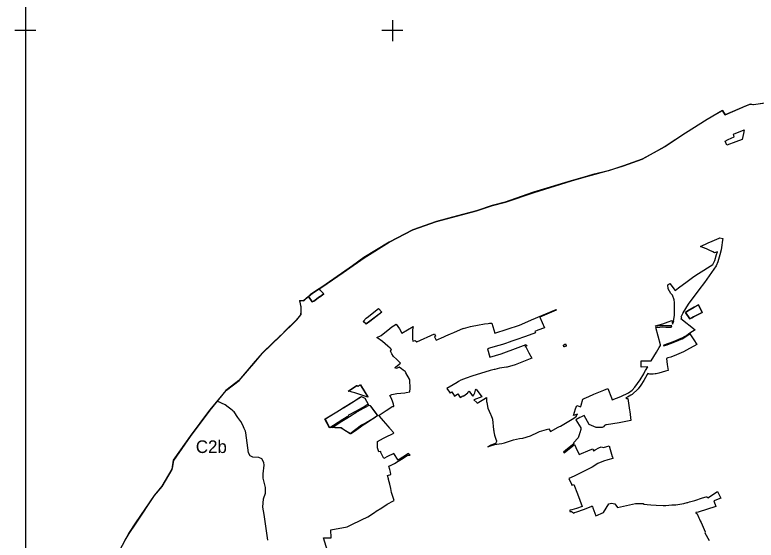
# Model space of a CAD drawing. Extents: x -478490 to -472450, y -1118050 to -1109550.
# Drawn here: x -478490 to -474975, y -1116218 to -1113725 of the extents above; entities that cross this region are included whole.
import ezdxf

# ---------------------------------------------------------------- set-up
doc = ezdxf.new("R2010")
doc.units = 0
for name, color, linetype in [('hranice kú', 7, 'Continuous'), ('Implicitní', 7, 'Continuous'), ('ObPÚ', 7, 'Continuous')]:
    doc.layers.add(name, color=color, linetype=linetype)

msp = doc.modelspace()

# ---------------------------------------------------------------- linework, layer by layer
at = {"layer": 'hranice kú'}
for p, q in [((-475022.9, -1114156.5), (-475122.4, -1114199.6)), ((-475002.4, -1114148.5), (-475022.9, -1114156.5)), ((-474987.2, -1114152.5), (-475002.4, -1114148.5)), ((-474886, -1114137.7), (-474987.2, -1114152.5)), ((-475134, -1114179), (-475207.8, -1114221.5)), ((-475122.4, -1114199.6), (-475134, -1114179)), ((-475207.8, -1114221.5), (-475309.6, -1114286.2)), ((-475309.6, -1114286.2), (-475401.1, -1114346.7)), ((-475401.1, -1114346.7), (-475408.2, -1114351.3)), ((-475408.2, -1114351.3), (-475516.2, -1114410.6)), ((-475516.2, -1114410.6), (-475603.8, -1114442.4)), ((-475603.8, -1114442.4), (-475675.9, -1114464.8)), ((-475748.8, -1114483.6), (-475774.2, -1114490.1)), ((-475675.9, -1114464.8), (-475748.8, -1114483.6)), ((-475851.9, -1114513.6), (-476030.1, -1114567.2)), ((-475774.2, -1114490.1), (-475851.9, -1114513.6)), ((-476089.1, -1114587.7), (-476165.8, -1114614.4)), ((-476030.1, -1114567.2), (-476089.1, -1114587.7)), ((-476165.8, -1114614.4), (-476226.9, -1114630.6)), ((-476300.5, -1114656.1), (-476390.6, -1114678.9)), ((-476226.9, -1114630.6), (-476300.5, -1114656.1)), ((-476390.6, -1114678.9), (-476491.3, -1114705.4)), ((-476491.3, -1114705.4), (-476602.9, -1114745.8)), ((-476602.9, -1114745.8), (-476714.7, -1114803.6)), ((-476714.7, -1114803.6), (-476835.3, -1114877.2)), ((-476835.3, -1114877.2), (-476889.8, -1114915.9)), ((-476889.8, -1114915.9), (-477034.1, -1115017.7)), ((-477079.5, -1115046.1), (-477089.2, -1115054.5)), ((-477047.8, -1115026.2), (-477079.5, -1115046.1)), ((-477034.1, -1115017.7), (-477047.8, -1115026.2)), ((-477121, -1115082.3), (-477141, -1115082)), ((-477141, -1115082), (-477133.6, -1115111.5)), ((-477098.4, -1115062.6), (-477121, -1115082.3)), ((-477089.2, -1115054.5), (-477098.4, -1115062.6)), ((-477133.6, -1115111.5), (-477134.2, -1115129.3)), ((-477134.7, -1115147.1), (-477142.3, -1115156.6)), ((-477134.2, -1115129.3), (-477134.7, -1115147.1)), ((-477155, -1115172.4), (-477210.7, -1115227.9)), ((-477142.3, -1115156.6), (-477155, -1115172.4)), ((-477233.1, -1115250.4), (-477267, -1115282.3)), ((-477229.4, -1115246.9), (-477233.1, -1115250.4)), ((-477216.6, -1115233.9), (-477229.4, -1115246.9)), ((-477214.6, -1115231.9), (-477216.6, -1115233.9)), ((-477210.7, -1115227.9), (-477214.6, -1115231.9)), ((-477267, -1115282.3), (-477317.9, -1115330.4)), ((-477317.9, -1115330.4), (-477350, -1115369.3)), ((-477350, -1115369.3), (-477428.5, -1115460.9)), ((-477428.5, -1115460.9), (-477490.1, -1115508.2)), ((-477490.1, -1115508.2), (-477566.2, -1115601.8)), ((-477566.2, -1115601.8), (-477658.2, -1115726.7)), ((-477658.2, -1115726.7), (-477738.5, -1115840.6)), ((-477738.5, -1115840.6), (-477743.9, -1115876.8)), ((-477745.7, -1115882.6), (-477792.7, -1115963.5)), ((-477743.9, -1115876.8), (-477745.7, -1115882.6)), ((-477792.7, -1115963.5), (-477829.2, -1116007.1)), ((-477829.2, -1116007.1), (-477917, -1116137.1)), ((-477917, -1116137.1), (-477949.4, -1116186.8)), ((-477949.4, -1116186.8), (-477967.8, -1116218.8))]:
    msp.add_line(p, q, dxfattribs=at)
at = {"layer": 'Implicitní'}
for p, q in [((-478440.1, -1113750.1), (-478440.1, -1113850.1)), ((-478440.1, -1113750.1), (-478440.1, -1113850.1)), ((-478440.1, -1113750.1), (-478440.1, -1113850.1)), ((-478440.1, -1113750.1), (-478440.1, -1113850.1)), ((-478440.1, -1113750.1), (-478440.1, -1113850.1)), ((-478440.1, -1113750.1), (-478440.1, -1113850.1)), ((-478440.1, -1113750.1), (-478440.1, -1113850.1)), ((-478440.1, -1113750.1), (-478440.1, -1113850.1)), ((-476700.1, -1113750.1), (-476700.1, -1113850.1)), ((-476700.1, -1113750.1), (-476700.1, -1113850.1)), ((-476700.1, -1113750.1), (-476700.1, -1113850.1)), ((-476700.1, -1113750.1), (-476700.1, -1113850.1)), ((-476700.1, -1113750.1), (-476700.1, -1113850.1)), ((-476700.1, -1113750.1), (-476700.1, -1113850.1)), ((-476700.1, -1113750.1), (-476700.1, -1113850.1)), ((-476700.1, -1113750.1), (-476700.1, -1113850.1)), ((-478390.1, -1113800.1), (-478490.1, -1113800.1)), ((-478390.1, -1113800.1), (-478490.1, -1113800.1)), ((-478390.1, -1113800.1), (-478490.1, -1113800.1)), ((-478390.1, -1113800.1), (-478490.1, -1113800.1)), ((-478390.1, -1113800.1), (-478490.1, -1113800.1)), ((-478390.1, -1113800.1), (-478490.1, -1113800.1)), ((-478390.1, -1113800.1), (-478490.1, -1113800.1)), ((-476650.1, -1113800.1), (-476750.1, -1113800.1)), ((-476650.1, -1113800.1), (-476750.1, -1113800.1)), ((-476650.1, -1113800.1), (-476750.1, -1113800.1)), ((-476650.1, -1113800.1), (-476750.1, -1113800.1)), ((-476650.1, -1113800.1), (-476750.1, -1113800.1)), ((-476650.1, -1113800.1), (-476750.1, -1113800.1)), ((-476650.1, -1113800.1), (-476750.1, -1113800.1))]:
    msp.add_line(p, q, dxfattribs=at)
msp.add_lwpolyline([(-478440.1, -1118000.1), (-472500.1, -1118000.1), (-472500.1, -1109600.1), (-478440.1, -1109600.1)], close=True, dxfattribs=at)
msp.add_lwpolyline([(-477290.1, -1116218.2), (-477307.4, -1116096.5), (-477314.6, -1116061), (-477310.7, -1116023), (-477302.3, -1115994.9), (-477301.2, -1115968), (-477312.4, -1115923.9), (-477312, -1115903.3), (-477307.7, -1115862), (-477309.2, -1115849), (-477319.7, -1115832.3), (-477333.1, -1115826.6), (-477361.3, -1115824.1), (-477373.9, -1115818.6), (-477382.1, -1115804.4), (-477394.5, -1115708.3), (-477396.9, -1115701.8), (-477398.4, -1115697.9), (-477402.6, -1115688.6), (-477408.8, -1115672.3), (-477418.7, -1115655), (-477432.4, -1115635.9), (-477450.9, -1115610.1), (-477455.1, -1115605.5), (-477460.2, -1115601.4), (-477465.7, -1115597.1), (-477478.8, -1115587.9), (-477493.1, -1115576.5), (-477530.1, -1115558.5)], dxfattribs=at)
at = {"layer": 'ObPÚ'}
for p, q in [((-476795.8, -1115142.9), (-476765.1, -1115119.2)), ((-476765.1, -1115119.2), (-476749.5, -1115136)), ((-476823.6, -1115164), (-476813.4, -1115156.5)), ((-476813.4, -1115156.5), (-476795.8, -1115142.9)), ((-476749.5, -1115136), (-476807.4, -1115179.7)), ((-476838.6, -1115180.4), (-476823.6, -1115164)), ((-476823.5, -1115192.3), (-476838.6, -1115180.4)), ((-476807.4, -1115179.7), (-476823.5, -1115192.3)), ((-476909, -1115510.7), (-476870.1, -1115484.8)), ((-476870.1, -1115484.8), (-476863.3, -1115487.6)), ((-476863.3, -1115487.6), (-476852.1, -1115480.5)), ((-476852.1, -1115480.5), (-476817.4, -1115537.3)), ((-476900.7, -1115512.2), (-476909, -1115510.7)), ((-476891.2, -1115515.2), (-476900.7, -1115512.2)), ((-476878.5, -1115519.2), (-476891.2, -1115515.2)), ((-476816.7, -1115540.2), (-476878.5, -1115519.2)), ((-476817.4, -1115537.3), (-476816.7, -1115540.2))]:
    msp.add_line(p, q, dxfattribs=at)
for points in [[(-477992.6, -1116266.4), (-477967.7, -1116217.9), (-477949, -1116186), (-477916, -1116136), (-477827.8, -1116006.6), (-477791.1, -1115962.3), (-477744.4, -1115881.6), (-477737.4, -1115839.5), (-477657.3, -1115725.4), (-477565.5, -1115600.8), (-477486.9, -1115507), (-477426, -1115461.1), (-477348, -1115368.5), (-477315.2, -1115330.2), (-477231.4, -1115250.6), (-477154.2, -1115173.6), (-477134.2, -1115148.8), (-477133.2, -1115130.3), (-477132.1, -1115111.9), (-477138.9, -1115081.3), (-477119.7, -1115082.7), (-477097.2, -1115062.7), (-477080.6, -1115086.8), (-477072.5, -1115083.8), (-477045.9, -1115063.6), (-477043.9, -1115064.1), (-477025.3, -1115049.6), (-477043.5, -1115030.7), (-477047.5, -1115026.1), (-477033.7, -1115018.2), (-476934, -1114947.9), (-476834.4, -1114877.8), (-476714.6, -1114803.8), (-476602.9, -1114745.9), (-476491.3, -1114705.5), (-476390.2, -1114678.8), (-476300.7, -1114655.7), (-476225.2, -1114630.7), (-476164.4, -1114614.7), (-476028.4, -1114567.7), (-475850.6, -1114513.7), (-475773.2, -1114490.1), (-475675.4, -1114464.4), (-475603.9, -1114441.6), (-475515.6, -1114410.1), (-475407.7, -1114350.6), (-475310.4, -1114285.4), (-475208.2, -1114220.8), (-475134, -1114178.4), (-475121.9, -1114199.1), (-475023.6, -1114156.4), (-475002.8, -1114148.9), (-474998, -1114149.5), (-474990.2, -1114150.6), (-474989.1, -1114150.8), (-474987.5, -1114151), (-474886.4, -1114137.2)], [(-475031.6, -1114270.7), (-475035.2, -1114288.3), (-475041.6, -1114317.3), (-475071, -1114328.2), (-475113.6, -1114343.8), (-475122.4, -1114325.3), (-475107.2, -1114316.9), (-475078.7, -1114304.2), (-475082.7, -1114291.8), (-475031.6, -1114270.7)], [(-475148.1, -1114784.1), (-475132.8, -1114786.1), (-475134.1, -1114794.3), (-475139.6, -1114829.2), (-475141.4, -1114840.6), (-475147, -1114864.5), (-475156.6, -1114896.8), (-475164.7, -1114915.7), (-475219.8, -1114995.7), (-475246.4, -1115030.8), (-475297.9, -1115099.1), (-475322.5, -1115139.2), (-475323.4, -1115141.1), (-475326.2, -1115147.8), (-475332.4, -1115160.1), (-475329.7, -1115162.2), (-475332.8, -1115166.5), (-475264.7, -1115220.3), (-475289.6, -1115235.6), (-475304.6, -1115246.6), (-475313.5, -1115251.8), (-475327.3, -1115259.4), (-475332.9, -1115262), (-475368.8, -1115277.8), (-475390.2, -1115285.2), (-475413.5, -1115293), (-475413.9, -1115295.5), (-475414.6, -1115296.5), (-475396.8, -1115290.7), (-475381.9, -1115285.4), (-475368.1, -1115280.4), (-475352.2, -1115273.9), (-475342, -1115269.3), (-475326, -1115262.1), (-475313, -1115254.8), (-475303.1, -1115249.2), (-475289.4, -1115239.2), (-475271.1, -1115267.1), (-475256.4, -1115289.3), (-475305.6, -1115316.7), (-475319, -1115324.5), (-475352.1, -1115339), (-475379.3, -1115349.1), (-475393.3, -1115353.4), (-475400.3, -1115356), (-475396.5, -1115385.4), (-475392.7, -1115413), (-475404.3, -1115416.8), (-475436.9, -1115425.3), (-475448.5, -1115428.4), (-475454.5, -1115429.6), (-475463.7, -1115430.8), (-475472.8, -1115431.1), (-475479.9, -1115430.5), (-475488.1, -1115428), (-475488.8, -1115427.8), (-475491.2, -1115432.3), (-475508.3, -1115461.2), (-475522.4, -1115482.1), (-475534.8, -1115500.6), (-475562.6, -1115526.6), (-475569.6, -1115530.7), (-475585.2, -1115539.6), (-475592.6, -1115543.6), (-475588.6, -1115546.6), (-475584.2, -1115546.5), (-475575.5, -1115600.7), (-475574.6, -1115607), (-475568.6, -1115650.4), (-475601.1, -1115656.6), (-475624.5, -1115661.2), (-475654.2, -1115666.4), (-475684.3, -1115671.3), (-475687.2, -1115670.6), (-475693.7, -1115674.8), (-475699, -1115680.1), (-475705.7, -1115683.9), (-475709.8, -1115683.9), (-475733.4, -1115683.1), (-475767, -1115669.8), (-475790, -1115626.6), (-475799.8, -1115631.5), (-475804, -1115633.4), (-475810.7, -1115636.7), (-475829.7, -1115648), (-475814.9, -1115672), (-475806.3, -1115684.8), (-475806.3, -1115693.2), (-475811.6, -1115709.7), (-475812.7, -1115712.9), (-475812.9, -1115713.5), (-475819.1, -1115732.4), (-475841.2, -1115755.7), (-475838.5, -1115760.3), (-475845.9, -1115766.1), (-475877.4, -1115790.5)], [(-475218.2, -1114832.5), (-475219.5, -1114831.9), (-475238.7, -1114824.8), (-475202.4, -1114807.1), (-475184, -1114798.8), (-475149.9, -1114784.6), (-475148.1, -1114784.1)], [(-476080.7, -1115733.9), (-476044.6, -1115722.8), (-476009.2, -1115705.3), (-476006, -1115704.3), (-476001.7, -1115702.9), (-475992.1, -1115700.1), (-475958.5, -1115689.8), (-475951, -1115702.6), (-475913.8, -1115682.5), (-475907.2, -1115679.6), (-475903.4, -1115677.7), (-475840.3, -1115639.7), (-475827.1, -1115629.9), (-475826.5, -1115627.2), (-475822.6, -1115620.1), (-475841.5, -1115626.4), (-475831.2, -1115595.6), (-475825.9, -1115579.1), (-475807.2, -1115585.2), (-475804.9, -1115577.5), (-475797.7, -1115549), (-475791.1, -1115546.2), (-475768.3, -1115535.9), (-475744.5, -1115525.5), (-475728.4, -1115519.2), (-475712.4, -1115512.7), (-475696.6, -1115506.6), (-475678, -1115499.1), (-475661.4, -1115542.5), (-475657.5, -1115552.7), (-475617.2, -1115536.5), (-475580, -1115519.1), (-475562.6, -1115505.8), (-475549.8, -1115492.6), (-475525.8, -1115458.2), (-475508.2, -1115428.6), (-475505.8, -1115425), (-475499.2, -1115413), (-475489.2, -1115395.3), (-475521.1, -1115396.7), (-475521.1, -1115367.4), (-475509.5, -1115367.4), (-475488.5, -1115367.2), (-475472.4, -1115366.6), (-475447.9, -1115326.5), (-475434.6, -1115304.4), (-475428.9, -1115294.7), (-475429.3, -1115291.8), (-475450.3, -1115208.5), (-475431.9, -1115206.9), (-475417.8, -1115206.3), (-475403.1, -1115207.2), (-475398.3, -1115207.7), (-475379.8, -1115208.2), (-475378.3, -1115208.3), (-475374.8, -1115201.4), (-475389.4, -1115201.4), (-475396.2, -1115201.5), (-475432.4, -1115201.7), (-475451.6, -1115203.6), (-475452.3, -1115200.8), (-475417.3, -1115191.5), (-475392.6, -1115182.3), (-475375.7, -1115175.9), (-475373.5, -1115183.9), (-475371.1, -1115193.9), (-475364.9, -1115179.2), (-475366.7, -1115178.5), (-475362.9, -1115152.1), (-475362.8, -1115131.7), (-475362.6, -1115116.2), (-475362.9, -1115105.9), (-475363, -1115101.2), (-475363, -1115098.2), (-475361.8, -1115090.2), (-475364.3, -1115077.5), (-475372.3, -1115055.4), (-475379.1, -1115047.3), (-475391.9, -1115024.9), (-475393.8, -1115006.5), (-475383.9, -1114999.9), (-475359.1, -1115032.8), (-475343.3, -1115021.2), (-475301.6, -1114990.1), (-475295.5, -1114985.5), (-475271.4, -1114967.5), (-475248.6, -1114952.7), (-475181.1, -1114910.8), (-475171.1, -1114890.7), (-475163.2, -1114863.4), (-475159.1, -1114849.7), (-475173.1, -1114854.9), (-475181, -1114850.7), (-475198.3, -1114841.7), (-475207.7, -1114837.2), (-475218.2, -1114832.5)], [(-477047.5, -1115026.1), (-477043.5, -1115030.7), (-477025.3, -1115049.6), (-477043.9, -1115064.1), (-477045.9, -1115063.6), (-477072.5, -1115083.8), (-477080.6, -1115086.8), (-477097.2, -1115062.7), (-477088.2, -1115054.8), (-477078.9, -1115046), (-477062.1, -1115035), (-477047.5, -1115026.1)], [(-476765.5, -1115119.5), (-476749.7, -1115136.3), (-476807.4, -1115180.3), (-476823.5, -1115192.5), (-476838.5, -1115180.6), (-476823.2, -1115163.8), (-476813.4, -1115156.1), (-476796, -1115142.8), (-476765.5, -1115119.5)], [(-476755.5, -1115799), (-476755.8, -1115798), (-476764.4, -1115799.6), (-476770.5, -1115780.2), (-476771, -1115765.2), (-476770.2, -1115749.7), (-476741.8, -1115734.8), (-476732, -1115729.7), (-476696.8, -1115711.7), (-476692.5, -1115709.2), (-476710.4, -1115689.4), (-476712.4, -1115687.1), (-476720, -1115678.1), (-476742.3, -1115651.6), (-476761.2, -1115630.1), (-476764.4, -1115626.4), (-476763, -1115625.6), (-476729.7, -1115602.9), (-476697.2, -1115582.4), (-476694.7, -1115586.2), (-476693.6, -1115580.2), (-476694.2, -1115572.8), (-476699.2, -1115558.8), (-476706, -1115542.3), (-476712.2, -1115531.2), (-476708.5, -1115529.6), (-476702.9, -1115527.4), (-476678.2, -1115523.1), (-476641.2, -1115518.6), (-476634.7, -1115517.8), (-476617.1, -1115514.8), (-476616.1, -1115497.4), (-476616.8, -1115459.6), (-476619.4, -1115454.6), (-476636.7, -1115424.2), (-476638.2, -1115419.2), (-476639.6, -1115417.9), (-476648.1, -1115411.8), (-476657.2, -1115405.2), (-476667.7, -1115397.8), (-476668.1, -1115397.6), (-476680.6, -1115404.3), (-476688.9, -1115400.3), (-476683.5, -1115395.6), (-476662.2, -1115377.8), (-476669.9, -1115369.8), (-476680.8, -1115358.9), (-476694.9, -1115346.1), (-476702.3, -1115334.6), (-476708.2, -1115320.9), (-476704.6, -1115313.1), (-476707.2, -1115310.4), (-476710.6, -1115306.8), (-476721, -1115296.9), (-476747.1, -1115275.5), (-476773.1, -1115256.3), (-476753.8, -1115247.8), (-476712.6, -1115214.6), (-476702.4, -1115206.3), (-476694.3, -1115201.1), (-476681.6, -1115192.9), (-476666.8, -1115216), (-476654.4, -1115235.6), (-476600.8, -1115204.3), (-476604, -1115219.8), (-476604.3, -1115242.1), (-476604.4, -1115257.8), (-476603.8, -1115263.8), (-476602.2, -1115273.2), (-476591.8, -1115271.3), (-476584.8, -1115277.5), (-476501, -1115239.4), (-476495.6, -1115250.2), (-476500.4, -1115252.6), (-476492.4, -1115268.6), (-476455.9, -1115252.7), (-476446, -1115248.3), (-476423.8, -1115238.9), (-476408.7, -1115232.4), (-476362.8, -1115211.5), (-476363.1, -1115214.2), (-476329.8, -1115204.9), (-476321.4, -1115203.2), (-476295.6, -1115198.1), (-476262.7, -1115192.2), (-476245.3, -1115189.6), (-476239, -1115188.4), (-476229.4, -1115189.3), (-476228.4, -1115189.3), (-476213.9, -1115236.2), (-476097.8, -1115198.2), (-476044, -1115174.6), (-476040.4, -1115173.1), (-475923.9, -1115123.8), (-475922.9, -1115126.6), (-476001.2, -1115160.1)], [(-476001.2, -1115160.1), (-475978.5, -1115210.4), (-476010.9, -1115222.5), (-476024.9, -1115227.8), (-476022.1, -1115234.1), (-476068.7, -1115252.3), (-476114.9, -1115267.7), (-476138.6, -1115276), (-476141.9, -1115277.2), (-476168.5, -1115286.4), (-476178.6, -1115289.9), (-476195.4, -1115294.7), (-476223, -1115302.6), (-476238.7, -1115307), (-476249.6, -1115310.1), (-476237.8, -1115350.3), (-476184.5, -1115334.3), (-476103.8, -1115304.7), (-476065.3, -1115290.1), (-476062.5, -1115296.4), (-476072.5, -1115299), (-476067.4, -1115300.8), (-476057.5, -1115319.9), (-476052.6, -1115329.4), (-476039.5, -1115354.8), (-476078.4, -1115369.8), (-476117, -1115385.5), (-476155.8, -1115397), (-476158.1, -1115397.3), (-476191.7, -1115401.9), (-476214.9, -1115407.7), (-476217.9, -1115408.5), (-476236.6, -1115413.2), (-476323, -1115439.7), (-476350.1, -1115449), (-476375, -1115459), (-476385.9, -1115464.8), (-476392.2, -1115469.7), (-476411, -1115480.8), (-476441.4, -1115498.3), (-476428.9, -1115516.6), (-476426.7, -1115520.2), (-476425.5, -1115519.4), (-476418.1, -1115514.4), (-476406.1, -1115534.8), (-476390, -1115524.6), (-476377.8, -1115542), (-476366.1, -1115533.4), (-476364.4, -1115535.6), (-476361.5, -1115533.8), (-476342.9, -1115519.2), (-476343.8, -1115517.9), (-476335.7, -1115511.8), (-476321.2, -1115532.1), (-476318.9, -1115534.9), (-476313, -1115528.6), (-476309.8, -1115518.6), (-476305.3, -1115506.9), (-476302.5, -1115502), (-476275.6, -1115537.5), (-476313.2, -1115552.2), (-476300.2, -1115565.6), (-476297.2, -1115568.2), (-476265.8, -1115548.7), (-476253.2, -1115541.5), (-476254.2, -1115545.1), (-476254.1, -1115560.3), (-476252.9, -1115565.5), (-476247.1, -1115591.9), (-476235, -1115620.9), (-476233.9, -1115623.6), (-476227.1, -1115639.9), (-476225.4, -1115644.4), (-476220, -1115694.3), (-476219.8, -1115696.3), (-476219.6, -1115698.6), (-476218.9, -1115704.2), (-476216.5, -1115719.8), (-476214.9, -1115724.1), (-476208.9, -1115738.8), (-476206.5, -1115747), (-476206.4, -1115750.3), (-476211.4, -1115759.3), (-476232.4, -1115767.1), (-476247.2, -1115775.1), (-476229.9, -1115769.6), (-476218.5, -1115766.3), (-476210.1, -1115762.7), (-476205.2, -1115762.3), (-476193.3, -1115761.9), (-476181.7, -1115759.9), (-476167.6, -1115755.9), (-476126.1, -1115741.6), (-476097.4, -1115735.9), (-476082.4, -1115734.1), (-476080.7, -1115733.9)], [(-475878.6, -1115287.3), (-475875.6, -1115294.7), (-475876.6, -1115295.2), (-475876.2, -1115296.1), (-475875.8, -1115297), (-475885.9, -1115301.2), (-475886.3, -1115300.2), (-475888.6, -1115293.7), (-475887, -1115293.1), (-475887.8, -1115291.1), (-475878.6, -1115287.3)], [(-476851.2, -1115480.9), (-476816.7, -1115537.6), (-476815.9, -1115540.5), (-476877.8, -1115519.3), (-476890.3, -1115515.3), (-476899.7, -1115512.3), (-476908, -1115510.6), (-476869, -1115484.9), (-476862.3, -1115487.4), (-476851.2, -1115480.9)], [(-476845.8, -1115536.8), (-476833.2, -1115543.1), (-476830.3, -1115545.2), (-476814.1, -1115573.4), (-476829.7, -1115582.6), (-476871.8, -1115606), (-476907.9, -1115625.4), (-476911.4, -1115631), (-476914.7, -1115633.2), (-476935, -1115646.2), (-476979.5, -1115674.5), (-476996.8, -1115685.2), (-477019.2, -1115643.1), (-476956.1, -1115604.4), (-476941.7, -1115595.5), (-476928.8, -1115587.7), (-476892.8, -1115565.7), (-476851.6, -1115540.4), (-476845.8, -1115536.8)], [(-476810.1, -1115578.3), (-476805.9, -1115579.4), (-476804.7, -1115580.3), (-476803.4, -1115582.1), (-476792.3, -1115597.6), (-476773.7, -1115623.2), (-476770.2, -1115628.1), (-476787.4, -1115639.3), (-476804.2, -1115650.6), (-476823.1, -1115663.3), (-476837.9, -1115672.8), (-476847.1, -1115679.5), (-476850.6, -1115681.9), (-476879.3, -1115702.4), (-476896.2, -1115714.4), (-476899, -1115714.2), (-476930.7, -1115694), (-476942.5, -1115685.1), (-476965.9, -1115685.2), (-476984.4, -1115683.5), (-476947.9, -1115658.3), (-476916.7, -1115638.9), (-476890.7, -1115623.1), (-476880.5, -1115616.9), (-476873.4, -1115612.5), (-476851.1, -1115600.2), (-476833, -1115590.3), (-476824.8, -1115585.7), (-476813, -1115578.7), (-476810.1, -1115578.3)], [(-475877.4, -1115790.5), (-475888.6, -1115801.4), (-475886, -1115804.2), (-475836, -1115764.4), (-475833.6, -1115770.2), (-475830.2, -1115777.9), (-475814.8, -1115812), (-475761.7, -1115789.4), (-475749.3, -1115784.9), (-475746.8, -1115794.7), (-475738, -1115789.5), (-475721.7, -1115779.9), (-475710.7, -1115775.7), (-475699.7, -1115779.1), (-475672.1, -1115771.2), (-475667.3, -1115787.5), (-475657.2, -1115821.4), (-475656.6, -1115823.4), (-475654.6, -1115830.4), (-475677.9, -1115836.7), (-475698.4, -1115843.4), (-475726.3, -1115854.9), (-475753.2, -1115871.8), (-475796.4, -1115894.5), (-475838.6, -1115914.6), (-475863.6, -1115925.3), (-475850.8, -1115952.1), (-475848.8, -1115957.6), (-475839.8, -1115954), (-475822.7, -1115998.9), (-475799.8, -1116058.4), (-475826.7, -1116067.4), (-475849.1, -1116073.9), (-475859, -1116076.8), (-475858.5, -1116081.8), (-475850.5, -1116082.4), (-475846, -1116085.5), (-475841.5, -1116090.5), (-475835.8, -1116087.6), (-475824.7, -1116084.4), (-475793.6, -1116073.2), (-475757.8, -1116058.6), (-475752.6, -1116055.2), (-475751.9, -1116056.2), (-475751.3, -1116058.9), (-475749.1, -1116064.3), (-475735.2, -1116103), (-475699, -1116087), (-475673.7, -1116045.3), (-475661.5, -1116042.2), (-475645.4, -1116045.7), (-475632.5, -1116062.8), (-475547.6, -1116045), (-475509.3, -1116044.8), (-475509.4, -1116046.9), (-475475.1, -1116050.7), (-475449.8, -1116052.2), (-475416.4, -1116053.9), (-475403.4, -1116053.3), (-475374.7, -1116051.3), (-475356.5, -1116050.4), (-475317.7, -1116043.9), (-475302.2, -1116039.9), (-475298.9, -1116039.2), (-475291.5, -1116036.7), (-475266.1, -1116030), (-475230.2, -1116017.8), (-475212.6, -1116013.1), (-475209, -1116012.4), (-475205, -1116017.9), (-475157.9, -1115986.7), (-475143.1, -1116018.7), (-475171.7, -1116030.3), (-475175.1, -1116031.6), (-475166.6, -1116058.8), (-475250, -1116085.1), (-475260.4, -1116087.5), (-475261.4, -1116089.2), (-475254.8, -1116092.9), (-475246.3, -1116113), (-475243.5, -1116119.3), (-475240.6, -1116126), (-475236.6, -1116135), (-475217.4, -1116178.1), (-475216.4, -1116180.6), (-475219.2, -1116183.5), (-475197.7, -1116219.3)], [(-477007.9, -1116269), (-477025.9, -1116207.4), (-476990.5, -1116207), (-476992.4, -1116169.7), (-476913.9, -1116154.4), (-476895, -1116145), (-476846.1, -1116121.6), (-476816.5, -1116106.9), (-476785, -1116086.7), (-476776.6, -1116081.3), (-476750.7, -1116064.8), (-476724.3, -1116048.2), (-476695, -1116031.9), (-476691.4, -1116029.9), (-476697.9, -1116011.9), (-476703.4, -1115992.7), (-476707.7, -1115973.2), (-476712.7, -1115953.4), (-476717.9, -1115931.2), (-476718.9, -1115926.7), (-476722.5, -1115911.7), (-476708, -1115906.3), (-476706.6, -1115905.8), (-476709.3, -1115896.3), (-476712.4, -1115883.4), (-476716.3, -1115867), (-476706.5, -1115862.8), (-476689.2, -1115855), (-476672.4, -1115844.1), (-476656.2, -1115833.3), (-476639.8, -1115822.5), (-476624.6, -1115814.3), (-476615.7, -1115814.8), (-476624, -1115806.8), (-476672.6, -1115838.9), (-476693.6, -1115807.2), (-476722.7, -1115821.8), (-476740.9, -1115830.8), (-476754.6, -1115802.9), (-476755.5, -1115799)]]:
    msp.add_lwpolyline(points, dxfattribs=at)
for points in [[(-475309.6, -1115137.3), (-475298.3, -1115130.6), (-475298.9, -1115129.2), (-475268.3, -1115111.9), (-475249.1, -1115101.1), (-475230.6, -1115137.3), (-475253.9, -1115149.2), (-475272, -1115158.9), (-475280.6, -1115163.6), (-475290, -1115168.6)], [(-475309.6, -1115137.3), (-475290, -1115168.6), (-475280.6, -1115163.6), (-475272, -1115158.9), (-475253.9, -1115149.2), (-475230.6, -1115137.3), (-475249.1, -1115101.1), (-475268.3, -1115111.9), (-475298.9, -1115129.2), (-475298.3, -1115130.6)], [(-476847.1, -1115536.5), (-476831.3, -1115545), (-476814.5, -1115573.1), (-476813.5, -1115578.5), (-476810.5, -1115578.2), (-476806.2, -1115579.8), (-476803.9, -1115582.7), (-476792.3, -1115597.2), (-476773, -1115622.4), (-476769.2, -1115626.6), (-476786.4, -1115638.9), (-476824.6, -1115661), (-476839.5, -1115669.7), (-476846, -1115673.3), (-476899.9, -1115714.2), (-476935.6, -1115692.1), (-476945.3, -1115684.7), (-476973.5, -1115685.2), (-476986, -1115684.2), (-476998.5, -1115686), (-477020.9, -1115643.5), (-476943, -1115597.1), (-476931.4, -1115590.2), (-476893.5, -1115566.1), (-476853.3, -1115540.3)]]:
    msp.add_lwpolyline(points, close=True, dxfattribs=at)

# ---------------------------------------------------------------- texts
at = {"layer": 'Implicitní'}
msp.add_text('C2b', height=60, dxfattribs=at).set_placement((-477632, -1115804.7))

doc.saveas('drawing.dxf')
